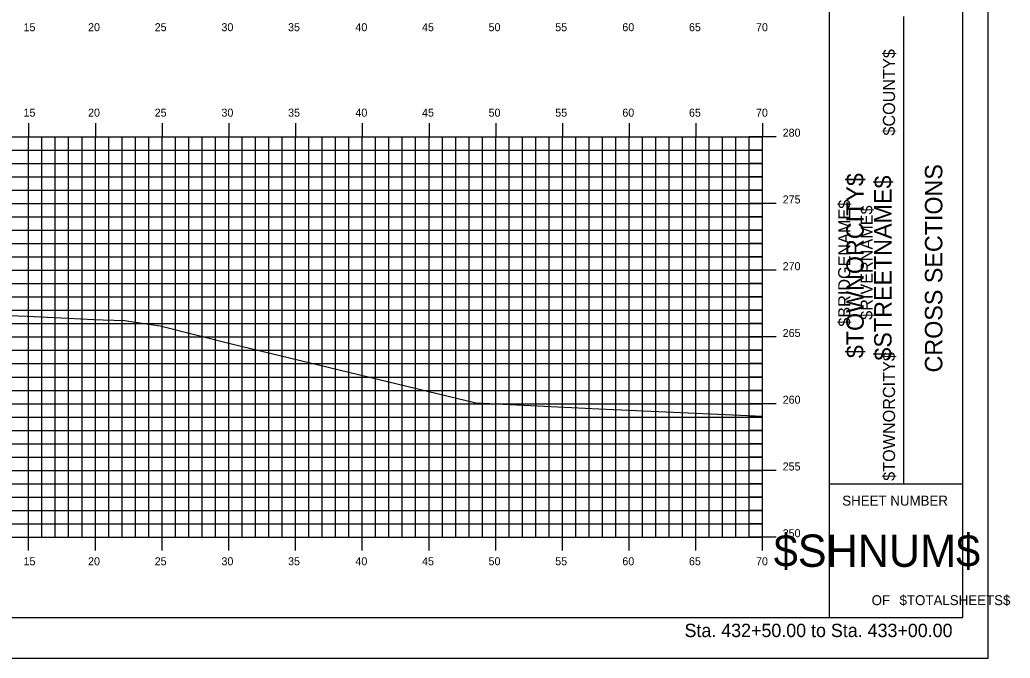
# Model space of a CAD drawing. Extents: x 1168600 to 1177589, y 610178 to 611246.
# Drawn here: x 1176308.5 to 1176382.7, y 610900.5 to 610948.3 of the extents above; entities that cross this region are included whole.
import ezdxf

# ---------------------------------------------------------------- set-up
doc = ezdxf.new("R2010")
doc.units = 0
for name, color, linetype in [('_Construction', 7, 'Continuous'), ('_Station Equation', 7, 'Continuous'), ('H_V ANNOTATION', 7, 'Continuous'), ('MAJOR', 7, 'Continuous'), ('MINOR', 7, 'Continuous')]:
    doc.layers.add(name, color=color, linetype=linetype)

msp = doc.modelspace()

# ---------------------------------------------------------------- linework, layer by layer
at = {"layer": '_Construction'}
for p, q in [((1176369.176, 610903.599), (1176369.176, 611008.599)), ((1176379.176, 610903.599), (1176379.176, 611008.599)), ((1176374.767, 610913.599), (1176374.767, 610948.599)), ((1176369.176, 610913.599), (1176379.176, 610913.599)), ((1176219.176, 610903.596), (1176379.176, 610903.596))]:
    msp.add_line(p, q, dxfattribs=at)
msp.add_lwpolyline([(1176211.083, 610900.537), (1176381.083, 610900.537), (1176381.083, 611010.537), (1176211.083, 611010.537)], close=True, dxfattribs=at)
at = {"layer": '_Station Equation'}
for points in [[(1176307.032, 610926.224), (1176309.071, 610926.166), (1176312.12, 610925.998), (1176314.072, 610925.899), (1176314.755, 610925.873), (1176316.39, 610925.82), (1176317.155, 610925.704), (1176317.696, 610925.617), (1176319.043, 610925.422), (1176324.367, 610924.093), (1176342.694, 610919.672), (1176351.892, 610919.212), (1176364.176, 610918.656)], [(1176307.033, 610926.224), (1176309.071, 610926.166), (1176312.121, 610925.998), (1176314.072, 610925.899), (1176314.755, 610925.873), (1176316.39, 610925.82), (1176317.155, 610925.704), (1176317.696, 610925.617), (1176319.043, 610925.422), (1176324.367, 610924.093), (1176342.694, 610919.672), (1176351.891, 610919.212), (1176364.176, 610918.656)]]:
    msp.add_lwpolyline(points, dxfattribs=at)
at = {"layer": 'MAJOR'}
for p, q in [((1176309.176, 610940.598), (1176309.176, 610939.596)), ((1176314.176, 610940.598), (1176314.176, 610939.596)), ((1176319.176, 610940.598), (1176319.176, 610939.596)), ((1176324.176, 610940.598), (1176324.176, 610939.596)), ((1176329.176, 610940.598), (1176329.176, 610939.596)), ((1176334.176, 610940.598), (1176334.176, 610939.596)), ((1176339.176, 610940.598), (1176339.176, 610939.596)), ((1176344.176, 610940.598), (1176344.176, 610939.596)), ((1176349.176, 610940.598), (1176349.176, 610939.596)), ((1176354.176, 610940.598), (1176354.176, 610939.596)), ((1176359.176, 610940.598), (1176359.176, 610939.596)), ((1176364.176, 610940.598), (1176364.176, 610939.596)), ((1176224.176, 610939.596), (1176364.176, 610939.596)), ((1176224.176, 610939.596), (1176364.176, 610939.596)), ((1176309.176, 610909.596), (1176309.176, 610939.596)), ((1176314.176, 610909.596), (1176314.176, 610939.596)), ((1176319.176, 610909.596), (1176319.176, 610939.596)), ((1176324.176, 610909.596), (1176324.176, 610939.596)), ((1176329.176, 610909.596), (1176329.176, 610939.596)), ((1176334.176, 610909.596), (1176334.176, 610939.596)), ((1176339.176, 610909.596), (1176339.176, 610939.596)), ((1176344.176, 610909.596), (1176344.176, 610939.596)), ((1176349.176, 610909.596), (1176349.176, 610939.596)), ((1176354.176, 610909.596), (1176354.176, 610939.596)), ((1176359.176, 610909.596), (1176359.176, 610939.596)), ((1176365.178, 610939.596), (1176363.174, 610939.596)), ((1176364.176, 610909.596), (1176364.176, 610939.596)), ((1176364.176, 610909.596), (1176364.176, 610939.596)), ((1176224.176, 610934.596), (1176364.176, 610934.596)), ((1176365.178, 610934.596), (1176363.174, 610934.596)), ((1176224.176, 610929.596), (1176364.176, 610929.596)), ((1176365.178, 610929.596), (1176363.174, 610929.596)), ((1176224.176, 610924.596), (1176364.176, 610924.596)), ((1176365.178, 610924.596), (1176363.174, 610924.596)), ((1176224.176, 610919.596), (1176364.176, 610919.596)), ((1176365.178, 610919.596), (1176363.174, 610919.596)), ((1176224.176, 610914.596), (1176364.176, 610914.596)), ((1176365.178, 610914.596), (1176363.174, 610914.596)), ((1176224.176, 610909.596), (1176364.176, 610909.596)), ((1176224.176, 610909.596), (1176364.176, 610909.596)), ((1176309.176, 610908.594), (1176309.176, 610909.596)), ((1176314.176, 610908.594), (1176314.176, 610909.596)), ((1176319.176, 610908.594), (1176319.176, 610909.596)), ((1176324.176, 610908.594), (1176324.176, 610909.596)), ((1176329.176, 610908.594), (1176329.176, 610909.596)), ((1176334.176, 610908.594), (1176334.176, 610909.596)), ((1176339.176, 610908.594), (1176339.176, 610909.596)), ((1176344.176, 610908.594), (1176344.176, 610909.596)), ((1176349.176, 610908.594), (1176349.176, 610909.596)), ((1176354.176, 610908.594), (1176354.176, 610909.596)), ((1176359.176, 610908.594), (1176359.176, 610909.596)), ((1176365.178, 610909.596), (1176363.174, 610909.596)), ((1176364.176, 610908.594), (1176364.176, 610909.596))]:
    msp.add_line(p, q, dxfattribs=at)
at = {"layer": 'MINOR'}
for p, q in [((1176310.176, 610909.596), (1176310.176, 610939.596)), ((1176311.176, 610909.596), (1176311.176, 610939.596)), ((1176312.176, 610909.596), (1176312.176, 610939.596)), ((1176313.176, 610909.596), (1176313.176, 610939.596)), ((1176315.176, 610909.596), (1176315.176, 610939.596)), ((1176316.176, 610909.596), (1176316.176, 610939.596)), ((1176317.176, 610909.596), (1176317.176, 610939.596)), ((1176318.176, 610909.596), (1176318.176, 610939.596)), ((1176320.176, 610909.596), (1176320.176, 610939.596)), ((1176321.176, 610909.596), (1176321.176, 610939.596)), ((1176322.176, 610909.596), (1176322.176, 610939.596)), ((1176323.176, 610909.596), (1176323.176, 610939.596)), ((1176325.176, 610909.596), (1176325.176, 610939.596)), ((1176326.176, 610909.596), (1176326.176, 610939.596)), ((1176327.176, 610909.596), (1176327.176, 610939.596)), ((1176328.176, 610909.596), (1176328.176, 610939.596)), ((1176330.176, 610909.596), (1176330.176, 610939.596)), ((1176331.176, 610909.596), (1176331.176, 610939.596)), ((1176332.176, 610909.596), (1176332.176, 610939.596)), ((1176333.176, 610909.596), (1176333.176, 610939.596)), ((1176335.176, 610909.596), (1176335.176, 610939.596)), ((1176336.176, 610909.596), (1176336.176, 610939.596)), ((1176337.176, 610909.596), (1176337.176, 610939.596)), ((1176338.176, 610909.596), (1176338.176, 610939.596)), ((1176340.176, 610909.596), (1176340.176, 610939.596)), ((1176341.176, 610909.596), (1176341.176, 610939.596)), ((1176342.176, 610909.596), (1176342.176, 610939.596)), ((1176343.176, 610909.596), (1176343.176, 610939.596)), ((1176345.176, 610909.596), (1176345.176, 610939.596)), ((1176346.176, 610909.596), (1176346.176, 610939.596)), ((1176347.176, 610909.596), (1176347.176, 610939.596)), ((1176348.176, 610909.596), (1176348.176, 610939.596)), ((1176350.176, 610909.596), (1176350.176, 610939.596)), ((1176351.176, 610909.596), (1176351.176, 610939.596)), ((1176352.176, 610909.596), (1176352.176, 610939.596)), ((1176353.176, 610909.596), (1176353.176, 610939.596)), ((1176355.176, 610909.596), (1176355.176, 610939.596)), ((1176356.176, 610909.596), (1176356.176, 610939.596)), ((1176357.176, 610909.596), (1176357.176, 610939.596)), ((1176358.176, 610909.596), (1176358.176, 610939.596)), ((1176360.176, 610909.596), (1176360.176, 610939.596)), ((1176361.176, 610909.596), (1176361.176, 610939.596)), ((1176362.176, 610909.596), (1176362.176, 610939.596)), ((1176363.176, 610909.596), (1176363.176, 610939.596)), ((1176224.176, 610938.596), (1176364.176, 610938.596)), ((1176364.176, 610938.596), (1176363.174, 610938.596)), ((1176224.176, 610937.596), (1176364.176, 610937.596)), ((1176364.176, 610937.596), (1176363.174, 610937.596)), ((1176224.176, 610936.596), (1176364.176, 610936.596)), ((1176364.176, 610936.596), (1176363.174, 610936.596)), ((1176224.176, 610935.596), (1176364.176, 610935.596)), ((1176364.176, 610935.596), (1176363.174, 610935.596)), ((1176224.176, 610933.596), (1176364.176, 610933.596)), ((1176364.176, 610933.596), (1176363.174, 610933.596)), ((1176224.176, 610932.596), (1176364.176, 610932.596)), ((1176364.176, 610932.596), (1176363.174, 610932.596)), ((1176224.176, 610931.596), (1176364.176, 610931.596)), ((1176364.176, 610931.596), (1176363.174, 610931.596)), ((1176224.176, 610930.596), (1176364.176, 610930.596)), ((1176364.176, 610930.596), (1176363.174, 610930.596)), ((1176224.176, 610928.596), (1176364.176, 610928.596)), ((1176364.176, 610928.596), (1176363.174, 610928.596)), ((1176224.176, 610927.596), (1176364.176, 610927.596)), ((1176364.176, 610927.596), (1176363.174, 610927.596)), ((1176224.176, 610926.596), (1176364.176, 610926.596)), ((1176364.176, 610926.596), (1176363.174, 610926.596)), ((1176224.176, 610925.596), (1176364.176, 610925.596)), ((1176364.176, 610925.596), (1176363.174, 610925.596)), ((1176224.176, 610923.596), (1176364.176, 610923.596)), ((1176364.176, 610923.596), (1176363.174, 610923.596)), ((1176224.176, 610922.596), (1176364.176, 610922.596)), ((1176364.176, 610922.596), (1176363.174, 610922.596)), ((1176224.176, 610921.596), (1176364.176, 610921.596)), ((1176364.176, 610921.596), (1176363.174, 610921.596)), ((1176224.176, 610920.596), (1176364.176, 610920.596)), ((1176364.176, 610920.596), (1176363.174, 610920.596)), ((1176224.176, 610918.596), (1176364.176, 610918.596)), ((1176364.176, 610918.596), (1176363.174, 610918.596)), ((1176224.176, 610917.596), (1176364.176, 610917.596)), ((1176364.176, 610917.596), (1176363.174, 610917.596)), ((1176224.176, 610916.596), (1176364.176, 610916.596)), ((1176364.176, 610916.596), (1176363.174, 610916.596)), ((1176224.176, 610915.596), (1176364.176, 610915.596)), ((1176364.176, 610915.596), (1176363.174, 610915.596)), ((1176224.176, 610913.596), (1176364.176, 610913.596)), ((1176364.176, 610913.596), (1176363.174, 610913.596)), ((1176224.176, 610912.596), (1176364.176, 610912.596)), ((1176364.176, 610912.596), (1176363.174, 610912.596)), ((1176224.176, 610911.596), (1176364.176, 610911.596)), ((1176364.176, 610911.596), (1176363.174, 610911.596)), ((1176224.176, 610910.596), (1176364.176, 610910.596)), ((1176364.176, 610910.596), (1176363.174, 610910.596))]:
    msp.add_line(p, q, dxfattribs=at)

# ---------------------------------------------------------------- texts
at = {"layer": '_Construction'}
for s, height, rotation, p in [('$COUNTY$', 0.9072, 90, (1176374.096, 610939.678)), ('$TOWNORCITY$', 1.30428, 90, (1176371.749, 610923.007)), ('CROSS SECTIONS', 1.30428, 90, (1176377.641, 610921.938)), ('$STREETNAME$', 1.30428, 90, (1176373.836, 610922.827)), ('$BRIDGENAME$', 0.90716, 90, (1176370.742, 610925.367)), ('$RIVERNAME$', 0.90716, 90, (1176372.419, 610925.882)), ('$TOWNORCITY$', 0.90716, 90, (1176374.096, 610913.82)), ('SHEET NUMBER', 0.74527, 360, (1176370.142, 610911.963)), ('$SHNUM$', 2.4194, 360, (1176365.009, 610907.379)), ('OF', 0.7453, 360, (1176372.343, 610904.509)), ('$TOTALSHEETS$', 0.74527, 360, (1176374.433, 610904.509))]:
    msp.add_text(s, height=height, rotation=rotation, dxfattribs=at).set_placement(p)
at = {"layer": 'H_V ANNOTATION'}
for s, height, p in [('15', 0.6, (1176308.793, 610947.496)), ('20', 0.6, (1176313.63, 610947.496)), ('25', 0.6, (1176318.622, 610947.496)), ('30', 0.6, (1176323.625, 610947.496)), ('35', 0.6, (1176328.617, 610947.496)), ('40', 0.6, (1176333.662, 610947.496)), ('45', 0.6, (1176338.654, 610947.496)), ('50', 0.6, (1176343.641, 610947.496)), ('55', 0.6, (1176348.633, 610947.496)), ('60', 0.6, (1176353.662, 610947.496)), ('65', 0.6, (1176358.654, 610947.496)), ('70', 0.6, (1176363.678, 610947.496)), ('15', 0.6, (1176308.793, 610941.096)), ('20', 0.6, (1176313.63, 610941.096)), ('25', 0.6, (1176318.622, 610941.096)), ('30', 0.6, (1176323.625, 610941.096)), ('35', 0.6, (1176328.617, 610941.096)), ('40', 0.6, (1176333.662, 610941.096)), ('45', 0.6, (1176338.654, 610941.096)), ('50', 0.6, (1176343.641, 610941.096)), ('55', 0.6, (1176348.633, 610941.096)), ('60', 0.6, (1176353.662, 610941.096)), ('65', 0.6, (1176358.654, 610941.096)), ('70', 0.6, (1176363.678, 610941.096)), ('280', 0.6, (1176365.676, 610939.596)), ('275', 0.6, (1176365.676, 610934.596)), ('270', 0.6, (1176365.676, 610929.596)), ('265', 0.6, (1176365.676, 610924.596)), ('260', 0.6, (1176365.676, 610919.596)), ('255', 0.6, (1176365.676, 610914.596)), ('250', 0.6, (1176365.676, 610909.596)), ('15', 0.6, (1176308.793, 610907.496)), ('20', 0.6, (1176313.63, 610907.496)), ('25', 0.6, (1176318.622, 610907.496)), ('30', 0.6, (1176323.625, 610907.496)), ('35', 0.6, (1176328.617, 610907.496)), ('40', 0.6, (1176333.662, 610907.496)), ('45', 0.6, (1176338.654, 610907.496)), ('50', 0.6, (1176343.641, 610907.496)), ('55', 0.6, (1176348.633, 610907.496)), ('60', 0.6, (1176353.662, 610907.496)), ('65', 0.6, (1176358.654, 610907.496)), ('70', 0.6, (1176363.678, 610907.496)), ('Sta. 432+50.00 to Sta. 433+00.00', 1.0002, (1176358.322, 610902.116))]:
    msp.add_text(s, height=height, dxfattribs=at).set_placement(p)

doc.saveas('drawing.dxf')
